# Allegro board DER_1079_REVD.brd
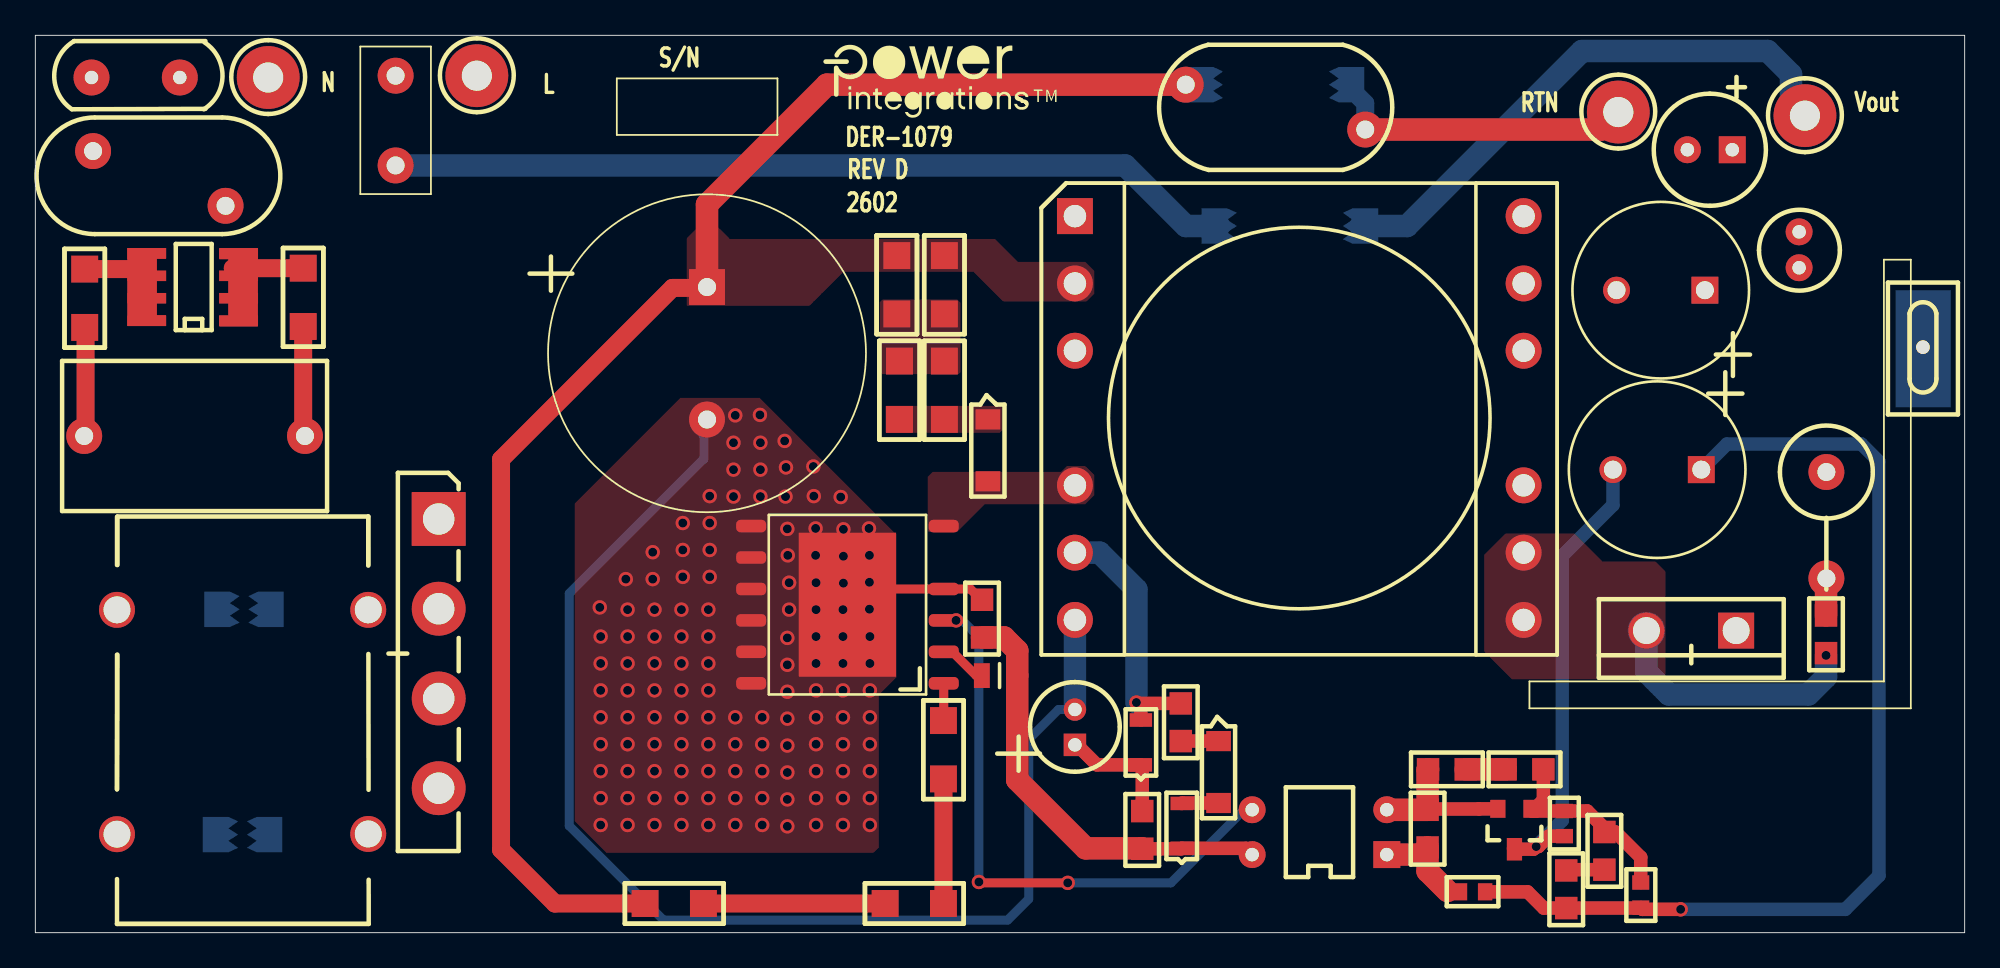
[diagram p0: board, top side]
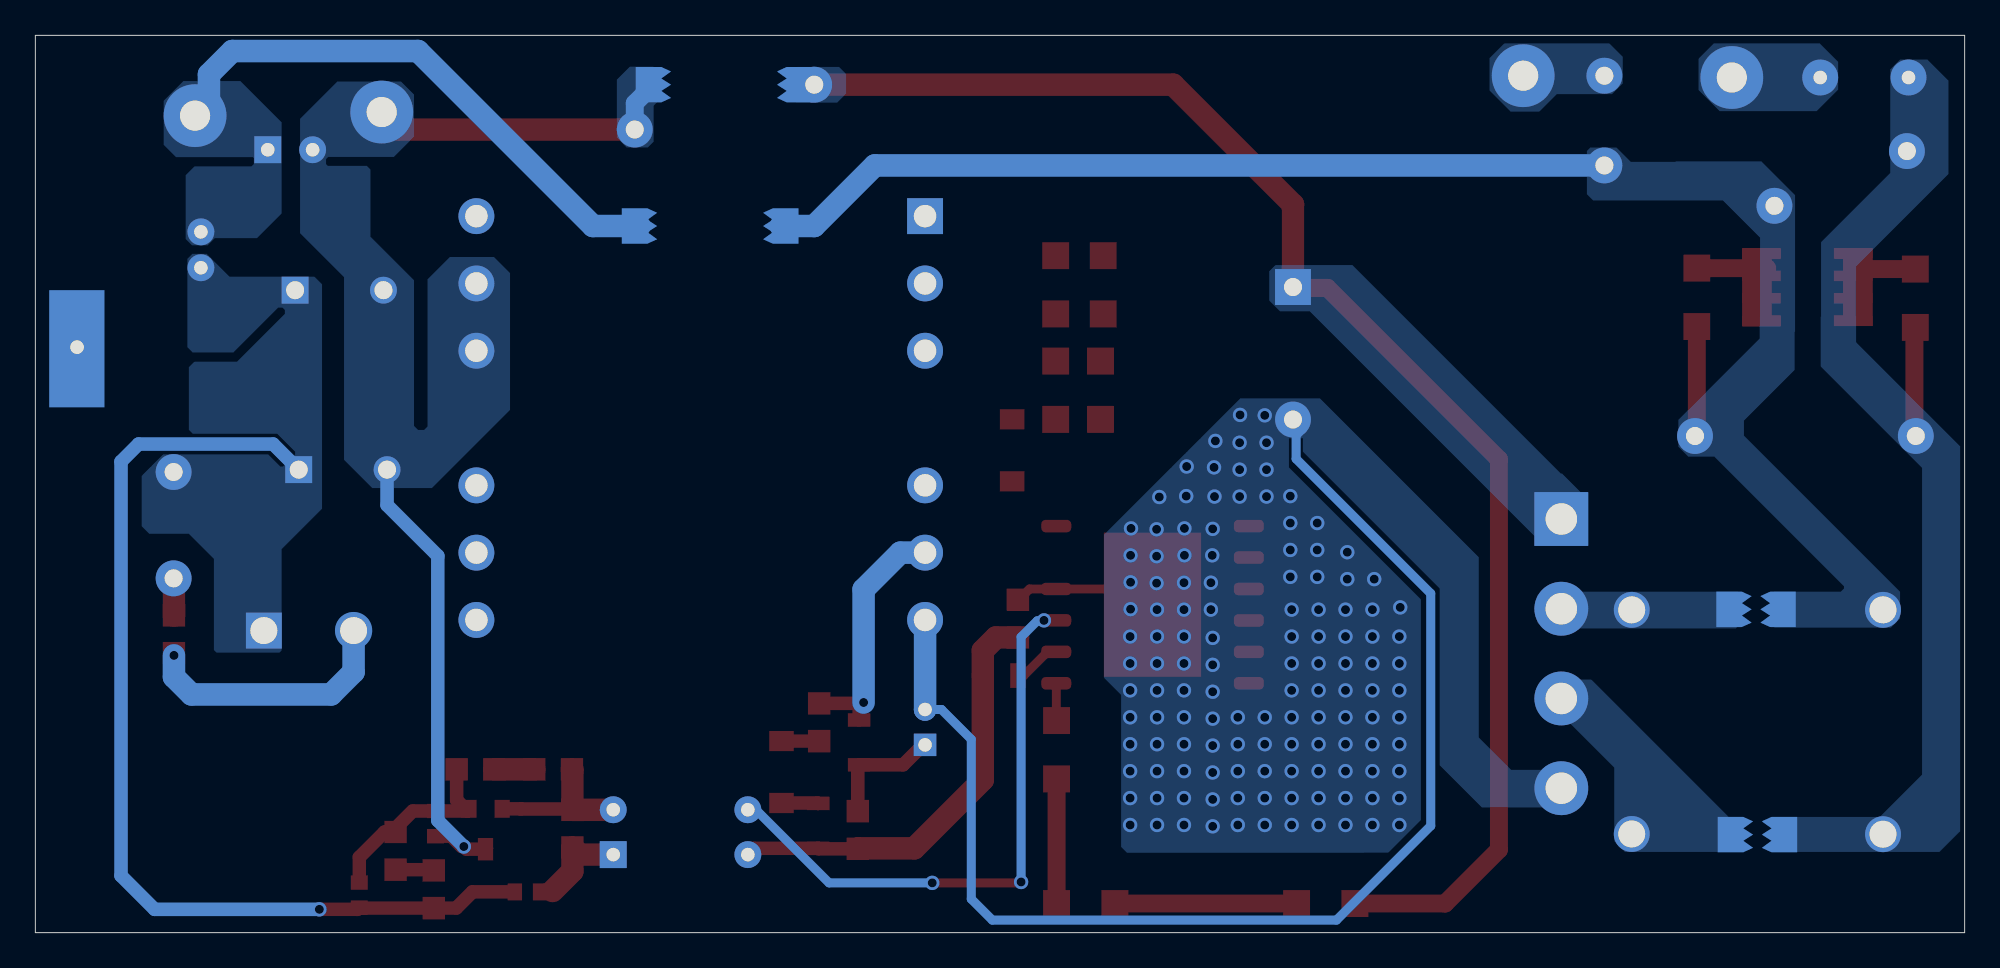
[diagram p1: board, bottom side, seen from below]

Outline 109.22 x 50.8 mm; copper layers: TOP, BOTTOM. Coordinates in mm from the lower left corner of the outline.
Outline path: 0,50.8 109.22,50.8 109.22,0 0,0 0,50.8

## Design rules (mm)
constraint set DEFAULT: min track width 0.508

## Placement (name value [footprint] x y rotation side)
BR1  GBU8K-BP  [PIDAXBRIDGEGBU8]  22.83 23.42 270 top
C1  330 nF  [PINP_XCAPRAD15X8P5X14HD040]  15.27 28.12 180 top
C2  150 uF  [PICAPCLY18X33P5MMV]  38.02 36.55 270 top
C3  1  nF  [PISMC1206]  51.46 38.33 270 top
C4  0.47 uF  [PISMC0805]  53.59 16.71 90 top
C6  22 uF  [PIPOLCAPCLYD5MMD030]  58.85 11.63 90 top
C8  2.2 nF  [PINPYCAPRAD540X290LS400040]  65.13 48.01 0 top
C10  1 nF  [PISMC0805]  101.37 15.82 90 top
C11  330 uF  [PIPOLCAPCLYD10MM040]  94.31 26.21 180 top
C12  330 uF  [PIPOLCAPCLYD10MM040]  94.51 36.37 180 top
C13  22 nF  [PISMC0805]  78.84 9.25 0 top
C16  10 nF  [PISMC0805]  88.82 3.57 90 top
C18  56 uF  [PIPOLCAPCYLD250LS100030]  96.06 44.32 180 top
D1  S1MLHRVG  [PI_SM_SOD-123_12]  53.92 29.06 270 top
D3  BAV21WS-7-F  [PISMSOD323]  64.9 4.78 90 top
D4  BAV21WS-7-F  [PISMSOD323]  62.59 9.5 90 top
D5  MBR10200_T0_00001  [PIDVT0220ACREVA]  96.28 17.1 180 top
F1  3.15 A  [PI_RST_MICROFUSE]  20.4 48.51 270 top
HS1  Terminal, Eyelet, Zierick 190  [PI_ZIERICK190_EYELET]  106.86 33.15 90 top
L1  42 Ohm  [INDC2012X105N]  54.58 14.55 0 top
L2  9 mH  [PI_TOROID_BALUN_1]  4.62 5.58 0 top
L4  1.0 uH  [PI_CHOKE_TOKIN_1]  99.85 37.64 90 top
NOREF  -  []  44.63 50.7 0 top
NOREF#2  -  []  -228.6 -144.78 0 top
NOREF#3  -  []  0 0 0 top
NOREF#4  -  []  109.22 0 90 top
NOREF#5  -  []  -150.78 54.23 0 top
R1  1 Meg  [PISMR1206]  15.16 34.32 90 top
R2  1 Meg  [PISMR1206]  2.79 37.57 270 top
R3  2.00 M  [PISMR1206]  34.52 1.65 0 top
R4  3.30 M  [PISMR1206]  48.11 1.65 0 top
R5  2.7 M  [PISMR1206]  51.41 8.7 90 top
R6  20  [PISMR1206]  51.46 32.36 270 top
R7  20  [PISMR1206]  48.92 32.36 270 top
R8  680 k  [PISMR1206]  48.77 38.33 270 top
R10  5.62 k  [PISMR0805]  62.66 4.75 90 top
R11  47.0  [PISMR0805]  64.85 12.98 270 top
R13  10  [PI2WVRESD200LS300D040]  101.39 26.08 270 top
R15  1 k  [PISMR0805]  78.82 4.82 90 top
R16  3.01 k  [PISMR0603]  82.07 2.31 180 top
R18  20 k  [PISMR0805]  83.24 9.25 0 top
R19  187 k  [PISMR0603]  90.88 1.42 90 top
R20  10 k  [PISMR0603]  86.56 6.89 270 top
R21  20 k  [PISMR0805]  86.66 1.39 90 top
RT1  2.5  [PI_RAD150X300LS200D030]  8.18 48.41 180 top
RV1  320 Vac  [PIDISC500X225LS335X140040]  10.77 41.15 180 top
SG3  0.5mm gap  [PI_SPARK_GAP_0P5MM]  11.81 18.3 180 bottom
SG4  0.5mm gap  [PI_SPARK_GAP_0P5MM]  11.73 5.55 180 bottom
SG5  6.0mm gap  [PI_SPARK_GAP_6P0MM]  70.23 48.01 0 bottom
SG6  6.0mm gap  [PI_SPARK_GAP_6P0MM]  71.02 40.01 0 bottom
T1  PQ26/20  [PI_BOBBIN_BPQ26_20_12P_2]  71.55 29.13 0 top
TP1  WHT  [PITPKEYSTONE125X125]  13.18 48.41 180 top
TP2  BLK  [PITPKEYSTONE125X125]  24.99 48.51 180 top
TP3  BLK  [PITPKEYSTONE125X125]  89.61 46.46 180 top
TP4  RED  [PITPKEYSTONE125X125]  100.18 46.25 180 top
U1  CAP300DG  [PI_IC_SMD_SO8_CAPZERO]  11.51 34.65 90 top
U2  TOP7074K  [PI_ESOP-12B]  45.97 18.57 90 top
U3  LTV817D  [PI_DIP4]  76.5 4.42 90 top
U4  LMV431AIMF  [PISMSOT23132]  82.79 7.01 180 top
VR1  MMSZ5239B-7-F  [PI_SM_SOD-123_12]  66.98 10.85 270 top

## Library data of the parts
BR1 = DISCRETE BRIDGE_+~~-: alternate symbols: (pidaxbridgegbu8_horz); room: 1
C1 = CAP NP: alternate symbols: (pinp_xcaprad15x8p5x14Hd040H); room: 1
C2 = CAP POL: alternate symbols: (picapcly18x33p5mmh); room: 1
C3 = CAP NP: room: 1
C4 = CAP NP: alternate symbols: (Unisem_RMCF0805UL); room: 1
C6 = CAP POL: alternate symbols: (pipolcapclyd5x11mmd030H); tolerance: 20; room: 1
C8 = CAP NP: alternate symbols: (pinpycaprad540x290ls400040h); room: 2
C10 = CAP NP: alternate symbols: (Unisem_RMCF0805UL,CC0805,pismc0805_1); room: 2
C11 C12 = CAP POL: alternate symbols: (pipolcapclyd395x630ls200030h); room: 2
C13 = CAP NP: alternate symbols: (Unisem_RMCF0805UL); room: 2
C16 = CAP NP: room: 2
C18 = CAP POL: alternate symbols: (pipolcapcyld250ls100030h); room: 2
D1 = DIODE: room: 1
D3 D4 = DIODE: alternate symbols: (SOD323_UL_IPC,pismsod323_1); room: 1
D5 = DIODE SCHOTTKY
F1 = FUSE: alternate symbols: (pirstmicrofusehoz); room: 1
HS1 = TERM EYLT
L1 = INDUCTOR_BEAD
L2 = INDUCTOR_4P_revG_1
L4 = INDUCTOR
R1-R8 = R: room: 1
R10 R11 = R: alternate symbols: (Unisem_RMCF0805UL); room: 1
R13 = R: alternate symbols: (pi2wresd200ls900d040,pi2wvresd200ls300d040,pi2wvresd200ls400d040)
R15 R18 = R: alternate symbols: (Unisem_RMCF0805UL); room: 2
R16 R19 R20 = R: alternate symbols: (Unisem_RMCF0603UL); room: 2
R21 = R: room: 2
RT1 = THERMISTOR: alternate symbols: (pirad400x300ls200040_h); room: 1
RV1 = VARISTOR: alternate symbols: (pi_rad450x550ls300d040_h); room: 1
SG3-SG6 = SPARK_GAP: room: 1
T1 = BPQ26/20_12P/GENERIC
TP1 TP2 = TESTPOINT: alternate symbols: (TP_5010-14); room: 1
TP3 TP4 = TESTPOINT: alternate symbols: (TP_5010-14); room: 2
U1 = CAPZero: room: 1
U2 = TOPSwitch-GaN_eSOP12B
U3 = OPTO_A_B
U4 = TL431/SOT-23_RCA
VR1 = DIODE_ZENER: room: 1

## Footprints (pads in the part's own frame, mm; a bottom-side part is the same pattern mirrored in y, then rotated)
INDC2012X105N
  rect 0.899x1.4 smd: 1(-1.001,0) 2(1.001,0)
PI2WVRESD200LS300D040
  round 2.032 hole 1.016: 1(0,0) 2(6.02,0)
PI_BOBBIN_BPQ26_20_12P_2
  rect 2.032x2.032 hole 1.27: 1(-12.7,11.43)
  round 2.032 hole 1.27: 2(-12.7,7.62) 3(-12.7,3.81) 4(-12.7,-3.81) 5(-12.7,-7.62) 6(-12.7,-11.43) 7(12.7,-11.43) 8(12.7,-7.62) 9(12.7,-3.81) 10(12.7,3.81) 11(12.7,7.62) 12(12.7,11.43)
PI_CHOKE_TOKIN_1
  round 1.524 hole 0.762: 1(0,0) 2(2.032,0)
PI_DIP4
  rect 1.524x1.524 hole 0.762: 1(0,0)
  round 1.524 hole 0.762: 2(2.54,0) 3(2.54,7.62) 4(0,7.62)
PI_ESOP-12B
  rrect 0.711x1.699 smd: 1(-4.45,-5.451) 2(-2.67,-5.451) 3(-0.889,-5.451) 4(0.889,-5.451) 6(4.45,-5.451) 7(4.45,5.451) 8(2.67,5.451) 9(0.889,5.451) 10(-0.889,5.451) 11(-2.67,5.451) 12(-4.45,5.451)
  rect 8.151x5.509 smd: 13(0,0)
PI_IC_SMD_SO8_CAPZERO
  rect 0.599x2.2 smd: 1(0,0) 2(1.27,0) 3(2.54,0) 4(3.81,0) 5(3.81,5.199) 6(2.54,5.199) 7(1.27,5.199) 8(0,5.199)
PI_RAD150X300LS200D030
  round 2.032 hole 0.762: 1(0,0) 2(4.999,0)
PI_RST_MICROFUSE
  round 2.032 hole 1.016: 1(0,0) 2(5.08,0)
PI_SM_SOD-123_12
  rect 1.143x1.397 smd: 1(0,0) 2(3.505,0)
PI_SPARK_GAP_0P5MM
  custom 0.5x0.5 smd: 1(-1.25,0) 2(1.25,0)
PI_SPARK_GAP_6P0MM
  custom 0.5x0.5 smd: 1(-4,0) 2(4,0)
PI_TOROID_BALUN_1
  round 2.032 hole 1.524: 1(0,0) 2(14.224,0.013) 3(14.224,12.7) 4(0,12.7)
PI_ZIERICK190_EYELET
  round 0.762 hole 0.762: 1(0,0)
PICAPCLY18X33P5MMV
  rect 2.032x2.032 hole 1.016: 1(0,0)
  round 2.032 hole 1.016: 2(7.501,0)
PIDAXBRIDGEGBU8
  rect 3.048x3.048 hole 1.778: 1(0,0)
  round 3.048 hole 1.778: 2(5.08,0) 3(10.16,0) 4(15.24,0)
PIDISC500X225LS335X140040
  round 2.032 hole 1.016: 1(0,0) 2(7.501,-3.099)
PIDVT0220ACREVA
  rect 2.032x2.032 hole 1.524: 1(0,0)
  round 2.032 hole 1.524: 2(5.08,0)
PINP_XCAPRAD15X8P5X14HD040
  round 2.032 hole 1.016: 1(0,0) 2(12.499,0)
PINPYCAPRAD540X290LS400040
  round 2.032 hole 1.016: 1(0,0) 2(10.16,-2.54)
PIPOLCAPCLYD5MMD030
  rect 1.27x1.27 hole 0.762: 1(-1.001,0)
  round 1.27 hole 0.762: 2(1.001,0)
PIPOLCAPCLYD10MM040
  rect 1.524x1.524 hole 1.016: 1(0,0)
  round 1.524 hole 1.016: 2(5.001,0)
PIPOLCAPCYLD250LS100030
  rect 1.524x1.524 hole 0.762: 1(0,0)
  round 1.524 hole 0.762: 2(2.54,0)
PISMC0805
  rect 1.27x1.27 smd: 1(0,0) 2(2.134,0)
PISMC1206
  rect 1.524x1.524 smd: 1(0,0) 2(3.302,0)
PISMR0603
  rect 0.813x0.965 smd: 1(0,0) 2(1.422,0)
PISMR0805
  rect 1.27x1.27 smd: 1(0,0) 2(2.134,0)
PISMR1206
  rect 1.524x1.524 smd: 1(0,0) 2(3.302,0)
PISMSOD323
  rect 0.762x1.27 smd: 1(0,0) 2(2.54,0)
PISMSOT23132
  rect 0.864x1.016 smd: 1(-1.88,0) 2(0,0)
  rect 0.864x1.27 smd: 3(-0.94,2.286)
PITPKEYSTONE125X125
  round 3.556 hole 1.702: 1(0,0)

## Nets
GND: BR1.4 C2.2 C4.2 C6.2 T1.6 U2.4 U2.7 U2.8 U2.9 U2.10 U2.11 U2.12 U2.13
SGND: C8.2 C11.2 C12.2 C18.2 R20.2 SG5.2 T1.10 T1.11 TP3.1 U4.3
BP: C4.1 D3.1 L1.2 R10.1 U3.4
C: U2.3 U3.3(E)
D: D1.2 T1.4 U2.6
DC_BUS: BR1.1 C2.1 C3.1 C8.1 R3.1 R8.1 SG5.1 T1.2
VOUT+: C11.1 C12.1 D5.1 L4.1 R13.1 R16.1 R19.1 R21.1
N9484136: R3.2 R4.1
N9484140: R4.2 R5.1
N12558827: C6.1 D4.1 R10.2
N12559431: D4.2 R11.1 T1.5
N12559644: C3.2 R6.1 R7.1 R8.2
N12560793: C10.1 D5.2 T1.7 T1.8
N12561948: C16.2 R18.2 R19.2 R20.1 U4.1(VREF)
N12562020: C13.1 R15.2 U3.2 U4.2
N12562074: R15.1 R16.2 U3.1
N12562376: C16.1 R21.2
N12562817: C13.2 R18.1
N12569802: F1.1 TP2.1
N12569814: RT1.1 TP1.1
N12570058: C1.1 F1.2 L2.4 R1.1 RV1.1 SG3.2 SG6.1
N12570065: C1.2 L2.1 R2.2 RT1.2 RV1.2 SG4.2
N12570840: BR1.2 L2.3 SG3.1
N12570848: BR1.3(AC2) L2.2(4) SG4.1
N12633188: C10.2 R13.2
N12979761: R1.2 U1.1 U1.2 U1.3 U1.4
N12979769: R2.1 U1.5 U1.6 U1.7 U1.8(NC8)
N12981657: R5.2 U2.1
N12986702: D1.1 R6.2 R7.2
N12993570: D3.2 VR1.2
N12993578: R11.2 VR1.1
N13029630: C18.1 L4.2 SG6.2 TP4.1
N13057131: L1.1 U2.2

Pads without a net: HS1 1; T1 1 3 9 12

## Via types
v1: diameter 0.813, hole 0.508, TOP to BOTTOM, 134 vias

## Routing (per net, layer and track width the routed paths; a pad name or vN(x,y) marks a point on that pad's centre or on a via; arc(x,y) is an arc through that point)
GND: length 80.9
  TOP w0.508: U2.13 46.86,19.46 U2.4 52.93,19.46 53.54,18.85 C4.2
  BOTTOM w0.508: C6.2 57.92,12.63 56.24,10.95 56.24,1.91 55.04,0.71 35.56,0.71 30.23,6.05 30.23,19.2 37.85,26.82 37.85,28.16 37.49,28.52 C2.2
  BOTTOM w1.27: T1.6 C6.2
  vias: v1(31.95,18.41) v1(32,16.76) v1(32,15.24) v1(32,13.72) v1(32,12.19) v1(32,10.67) v1(32,9.14) v1(32,7.62) v1(32,6.1) v1(33.43,20.02) v1(33.53,18.29) v1(33.53,16.76) v1(33.53,15.24) v1(33.53,13.72) v1(33.53,12.19) v1(33.53,10.67) v1(33.53,9.14) v1(33.53,7.62) v1(33.53,6.1) v1(34.95,21.54) v1(34.95,20.02) v1(35.05,18.29) v1(35.05,16.76) v1(35.05,15.24) v1(35.05,13.72) v1(35.05,12.19) v1(35.05,10.67) v1(35.05,9.14) v1(35.05,7.62) v1(35.05,6.1) v1(36.58,18.29) v1(36.58,16.76) v1(36.58,15.24) v1(36.58,13.72) v1(36.58,12.19) v1(36.58,10.67) v1(36.58,9.14) v1(36.58,7.62) v1(36.58,6.1) v1(36.65,23.19) v1(36.65,21.67) v1(36.65,20.14) v1(38.1,18.29) v1(38.1,16.76) v1(38.1,15.24) v1(38.1,13.72) v1(38.1,12.19) v1(38.1,10.67) v1(38.1,9.14) v1(38.1,7.62) v1(38.1,6.1) v1(38.18,24.71) v1(38.18,23.19) v1(38.18,21.67) v1(38.18,20.14) v1(39.52,27.74) v1(39.52,26.21) v1(39.52,24.69) v1(39.62,29.29) v1(39.62,12.19) v1(39.62,10.67) v1(39.62,9.14) v1(39.62,7.62) v1(39.62,6.1) v1(41.02,29.31) v1(41.05,27.74) v1(41.05,26.21) v1(41.05,24.69) v1(41.15,12.19) v1(41.15,10.67) v1(41.15,9.14) v1(41.15,7.62) v1(41.15,6.1) v1(42.42,27.84) v1(42.49,26.34) v1(42.47,24.69) v1(42.57,22.86) v1(42.6,21.36) v1(42.57,16.69) v1(42.57,15.16) v1(42.57,13.64) v1(42.57,12.12) v1(42.57,10.59) v1(42.57,9.07) v1(42.57,7.54) v1(42.57,6.02) v1(42.67,19.81) v1(42.67,18.29) v1(44.04,26.39) v1(44.07,24.71) v1(44.17,22.89) v1(44.17,21.36) v1(44.2,19.81) v1(44.2,18.29) v1(44.2,16.76) v1(44.2,15.24) v1(44.2,13.72) v1(44.2,12.19) v1(44.2,10.67) v1(44.2,9.14) v1(44.2,7.62) v1(44.2,6.1) v1(45.59,24.66) v1(45.75,22.83) v1(45.75,21.31) v1(45.75,19.79) v1(45.72,18.29) v1(45.72,16.76) v1(45.72,15.24) v1(45.72,13.72) v1(45.72,12.19) v1(45.72,10.67) v1(45.72,9.14) v1(45.72,7.62) v1(45.72,6.1) v1(47.19,22.89) v1(47.22,21.36) v1(47.22,19.84) v1(47.22,18.31) v1(47.24,16.76) v1(47.24,15.24) v1(47.24,13.72) v1(47.24,12.19) v1(47.24,10.67) v1(47.24,9.14) v1(47.24,7.62) v1(47.24,6.1)
SGND: length 44.1
  TOP w0.762: 83.68,4.78 U4.3 84.81,4.72 v1(84.96,4.88) 85.08,4.88 85.67,5.47 R20.2
  TOP w1.27: TP3.1 88.62,45.47 C8.2
  BOTTOM w0.762: C11.2 89.31,24.21 86.44,21.33 86.44,6.35 v1(84.96,4.88)
  BOTTOM w1.016: SG5.2 75.29,46.95 C8.2
  BOTTOM w1.27: 75.3,45.45 C8.2
BP: length 24.7
  TOP w0.762: R10.1 64.87,4.75 D3.1 68.53,4.78 U3.4
  TOP w1.27: C4.1 54.84,16.71 55.59,15.97 L1.2 55.59,8.65 59.46,4.78 62.64,4.78 R10.1
C: length 32.8
  TOP w0.508: v1(58.45,2.82) 53.47,2.82 v1(53.42,2.87)
  BOTTOM w0.508: v1(53.42,2.87) 53.42,16.74 52.5,17.65 52.15,17.65 v1(52.12,17.68) ; v1(58.45,2.82) 64.29,2.82 68.43,6.96 U3.3
DC_BUS: length 82.9
  TOP w1.016: C2.1 37.97,36.5 36.07,36.5 26.37,26.8 26.37,4.7 29.41,1.65 R3.1
  TOP w1.27: C8.1 44.81,48.01 38.02,41.22 C2.1
  BOTTOM w0.762: SG5.1 C8.1
VOUT+: length 58
  TOP w0.762: v1(93.14,1.32) 90.98,1.32 R19.1 90.86,1.39 R21.1 85.39,1.39 84.48,2.31 R16.1
  BOTTOM w0.762: v1(93.14,1.32) 102.46,1.32 104.37,3.23 104.37,26.67 103.38,27.66 95.76,27.66 C11.1
N9484136: length 10.3
  TOP w1.016: R3.2 R4.1
N9484140: length 7.1
  TOP w1.016: R4.2 R5.1
N12558827: length 6.9
  TOP w0.762: R10.2 62.66,9.42 D4.1 60.1,9.5 58.96,10.63 C6.1
N12559431: length 14.3
  TOP w0.762: R11.1 62.38,12.98 ; 62.38,12.98 62.59,12.78 D4.2 ; 62.38,12.98 v1(62.33,13.03)
  BOTTOM w1.27: v1(62.33,13.03) 62.33,19.43 60.25,21.51 T1.5
N12560793: length 14.7
  BOTTOM w1.27: v1(101.37,15.7) 101.37,14.48 100.38,13.49 92.47,13.49 91.2,14.76 D5.2
N12561948: length 11.5
  TOP w0.762: 84.75,6.89 R20.1 87.85,6.89 88.82,5.92 C16.2 89.45,5.7 90.88,4.27 R19.2 ; 84.75,6.89 84.67,6.97 U4.1 ; 84.75,6.89 85.37,7.5 R18.2
N12562020: length 8.6
  TOP w0.762: U4.2 81.73,7.01 81.72,7 78.86,7 R15.2
  TOP w1.27: U3.2 76.51,6.95 R15.2 78.82,9.22 C13.1
N12562074: length 6.1
  TOP w0.508: R16.2 79.98,2.31 79.94,2.36
  TOP w1.27: 79.94,2.36 78.82,3.48 R15.1 78.41,4.42 U3.1
N12562376: length 2.2
  TOP w0.762: C16.1 86.71,3.57 R21.2
N12562817: length 2.3
  TOP w1.27: R18.1 C13.2
N12570058: length 54.7
  TOP w1.016: C1.1 15.16,28.22 R1.1
  BOTTOM w1.27: SG6.1 65.13,40.01 61.7,43.43 F1.2 20.57,43.61 20.73,43.46
N12570065: length 6.7
  TOP w0.508: 3.18,44.34 RV1.2 ; 2.77,27.74 C1.2
  TOP w1.016: R2.2 2.84,34.21 2.84,28.2 C1.2
N12633188: length 2.1
  TOP w1.27: R13.2 101.37,20.04 C10.2
N12979761: length 4
  TOP w1.016: R1.2 11.18,37.62
N12979769: length 3.5
  TOP w1.016: 6.22,37.39 6.05,37.57 R2.1
N12981657: length 2.1
  TOP w0.508: R5.2 51.42,12.02 U2.1
N12993570: length 2.1
  TOP w0.762: VR1.2 64.92,7.34 D3.2
N12993578: length 2.1
  TOP w0.762: R11.2 VR1.1
N13029630: length 31.8
  BOTTOM w1.27: SG6.2 77.65,40.01 87.56,49.91 98.07,49.91 99.39,48.59 99.39,46.71 TP4.1
N13057131: length 2.7
  TOP w0.508: L1.1 53.26,14.55 51.92,15.9 U2.2

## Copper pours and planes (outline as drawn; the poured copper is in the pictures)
GND on TOP: 48.74,14.45 47.75,13.46 47.75,4.83 47.45,4.52 32.33,4.52 30.53,6.32 30.53,24.28 36.53,30.28 41,30.28 48.74,22.53
GND on BOTTOM: 48.72,14.43 47.75,13.46 47.75,4.85 47.42,4.52 33.99,4.52 33.97,4.53 32.63,4.53 30.78,6.38 30.78,18.87 38.25,26.34 38.25,27.97 38.23,27.99 37.47,27.99 37.47,27.23 29.72,19.48 29.72,9.47 27.33,7.09 22.33,7.09 21.82,7.59 21.82,8.61 22.43,9.22 25.68,9.22 27.51,11.05 27.51,21.26 36.5,30.25 41,30.25 48.72,22.53
SGND on BOTTOM: 74.22,49.02 75.56,49.02 76.3,48.29 76.3,45.01 75.74,44.45 74.55,44.45 74.22,44.78 74.22,46.81 74.04,46.99 74.04,48.84
SGND on BOTTOM: 83.26,38.25 85.75,38.25 87.02,36.98 87.02,28.65 87.21,28.46 87.55,28.46 87.78,28.69 87.78,36.93 90.25,39.4 90.25,43.21 90.45,43.41 92.66,43.41 92.76,43.51 92.76,43.79 92.63,43.92 88.93,43.92 87.78,45.06 87.78,47.45 88.52,48.18 92.13,48.18 94.23,46.08 94.23,39.6 91.74,37.11 91.74,26.77 90.14,25.17 86.77,25.17 82.35,29.59 82.35,37.34
D on TOP: 50.52,25.81 50.8,26.09 58.06,26.09 58.39,26.42 59.44,26.42 59.94,25.91 59.94,24.77 59.44,24.26 53.75,24.26 52.17,22.68 50.6,22.68 50.52,22.76
DC_BUS on TOP: 45.75,37.41 53.11,37.41 54.79,35.74 59.51,35.74 59.94,36.17 59.94,37.47 59.44,37.97 55.63,37.97 54.33,39.27 39.32,39.27 38.4,40.18 37.74,40.18 36.88,39.32 36.88,35.48 43.81,35.48
DC_BUS on BOTTOM: 21.72,22.35 21.72,24.92 22.8,26 22.86,26 34.66,37.8 39.01,37.8 39.37,37.44 39.37,35.79 38.76,35.18 37.08,35.18 24.18,22.28 21.79,22.28
DC_BUS on BOTTOM: 63.83,46.99 66.12,46.99 66.14,47.02 66.14,48.95 66.08,49.01 63.72,49.01 63.32,48.62 63.32,47.5
Net_39 on BOTTOM (solid shape): 108.43,29.74 105.31,29.74 105.31,36.37 108.43,36.37
VOUT+ on BOTTOM: 92.99,24 92.99,36.7 93.42,37.13 98.22,37.13 99.52,38.43 100.33,38.43 100.61,38.15 100.61,33.15 100.3,32.84 98.02,32.84 95.48,35.38 95.22,35.38 95.1,35.26 95.1,35.03 97.8,32.32 100.22,32.32 100.53,32 100.53,28.47 100.3,28.24 95.53,28.24 94.51,27.23 94.51,27.08 95.2,26.39 95.35,26.39 96.04,27.08 101.98,27.08 103.2,25.86 103.2,23.01 102.77,22.58 100.53,22.58 99.11,21.16 99.11,16 98.96,15.85 95.4,15.85 95.28,15.98 95.28,21.72
N12559644 on TOP: 52.2,35.84 47.96,35.84 47.8,35.69 47.8,31.75 47.93,31.62 52.27,31.62 52.37,31.72 52.37,35.66
N12560793 on TOP: 92.05,14.4 92,14.35 83.59,14.35 82.02,15.93 82.02,21.39 83.22,22.59 87.13,22.59 88.72,21.01 91.72,21.01 92.28,20.45 92.28,14.61 92.08,14.4
N12569802 on BOTTOM: 20.12,50.34 26.06,50.34 26.9,49.5 26.9,47.68 25.7,46.48 24.08,46.48 23.09,47.47 19.96,47.47 19.35,48.08 19.35,49.58
N12569814 on BOTTOM: 14.2,50.34 8.2,50.34 7.16,49.3 7.16,47.73 8.38,46.51 13.87,46.51 15.06,47.7 15.06,49.48
N12570058 on BOTTOM: 9.6,41.76 11.51,43.66 16.36,43.66 16.38,43.64 18.9,43.64 19.71,44.45 21.18,44.45 21.39,44.25 21.39,41.81 21.03,41.45 13.69,41.45 11.58,39.34 11.58,33.96 11.53,33.91 9.73,33.91 9.6,34.04
N12570058 on BOTTOM: 9.63,34.85 11.61,34.85 11.61,33.63 16.21,29.03 16.21,27.51 15.65,26.95 14.17,26.95 6.83,19.61 6.83,19.48 7.01,19.3 10.79,19.3 10.82,19.28 10.82,17.32 10.77,17.27 4.17,17.27 3.66,17.78 3.66,19.3 12.5,28.14 12.5,28.98 9.63,31.85
N12570065 on BOTTOM: 8.15,32.05 2.41,26.31 2.41,8.94 4.8,6.55 10.72,6.55 10.72,4.57 1.42,4.57 0.25,5.74 0.25,27.53 6.15,33.43 6.15,34.87 8.15,34.87
N12570065 on BOTTOM: 4.22,48.87 4.22,43 8.13,39.09 8.13,34.54 7.7,34.11 6.17,34.11 6.17,36.88 6.15,36.91 6.15,37.72 0.91,42.95 0.91,48.23 2.11,49.43 3.66,49.43
N12570840 on BOTTOM: 12.8,19.3 12.8,17.37 12.95,17.22 23.85,17.22 24.18,17.55 24.18,19.1 23.98,19.3
N12570848 on BOTTOM: 12.7,6.55 13.36,6.55 21.13,14.33 23.65,14.33 24.03,13.94 24.03,12.7 23.52,12.19 22.68,12.19 19.84,9.35 19.84,5.18 19.23,4.57 12.7,4.57
N12979761 on TOP (solid shape): 12.6,34.32 10.41,34.32 10.41,34.92 10.92,34.92 10.92,38.13 10.41,38.13 10.41,38.73 12.6,38.73
N12979769 on TOP (solid shape): 7.39,38.15 6.88,38.15 6.88,34.95 7.39,34.95 7.39,34.34 5.21,34.34 5.21,38.76 7.39,38.76
N12986702 on TOP: 48.13,29.82 54.64,29.82 54.91,29.54 54.91,28.63 54.58,28.3 48.13,28.3
N13029630 on BOTTOM: 99.06,39.32 96.67,39.32 95.28,40.72 95.28,45.87 97.61,48.21 100.84,48.21 101.96,47.09 101.96,44.6 101.26,43.9 96.91,43.9 96.85,43.84 96.85,43.51 96.98,43.38 100.2,43.38 100.71,42.88 100.71,39.27 100.36,38.91 99.47,38.91

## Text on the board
Ref Des/Silkscreen Top: N | L | S/N | DER-1079 | 2602 | REV D | RTN | Vout
User.5: 14.  FAB HOUSE LOGO,DATE CODE TO BE IN SILK SCREEN ONLY.DO NOT USE COPPER. | 13.  MATERIAL FR4 COPPER 2oz THICKNESS 0.062" | PLEASE DELETE THESE PINS | NON-PLATED SLOT
User.8: FIGURE | FINISHED_SIZE | 20.0 | 30.0 | 40.0 | 50.0 | 60.0 | 67.0 | 70.0 | DRILL CHART: TOP to BOTTOM | ALL UNITS ARE IN MILS | TOLERANCE_DRILL | +3.0/-3.0 | PLATED | QTY | 134 | 13 | 16 | 12 | 6 | 4 | 189 | TOTAL HOLES:
